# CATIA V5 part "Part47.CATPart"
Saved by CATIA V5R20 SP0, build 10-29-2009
Part number: IA 2275SF
Revision: ANY
Definition: UNKNOWN
Nomenclature: IA 2275SF
Source: Unknown
Bounding box of the stored display mesh (mm): x -1.102 to 1.102, y -0.001 to 7.75, z -1.102 to 1.102
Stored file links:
  C:\Users\Utente\Desktop\IO LAVORO\3D X SITO CF\CUMSA\3D files FA\FA 042204-20\Part47.CATPart

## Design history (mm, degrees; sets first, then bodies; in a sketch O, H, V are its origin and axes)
Body1 "Cortar-Extruir2" (main body)
  Solid1: solid without history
